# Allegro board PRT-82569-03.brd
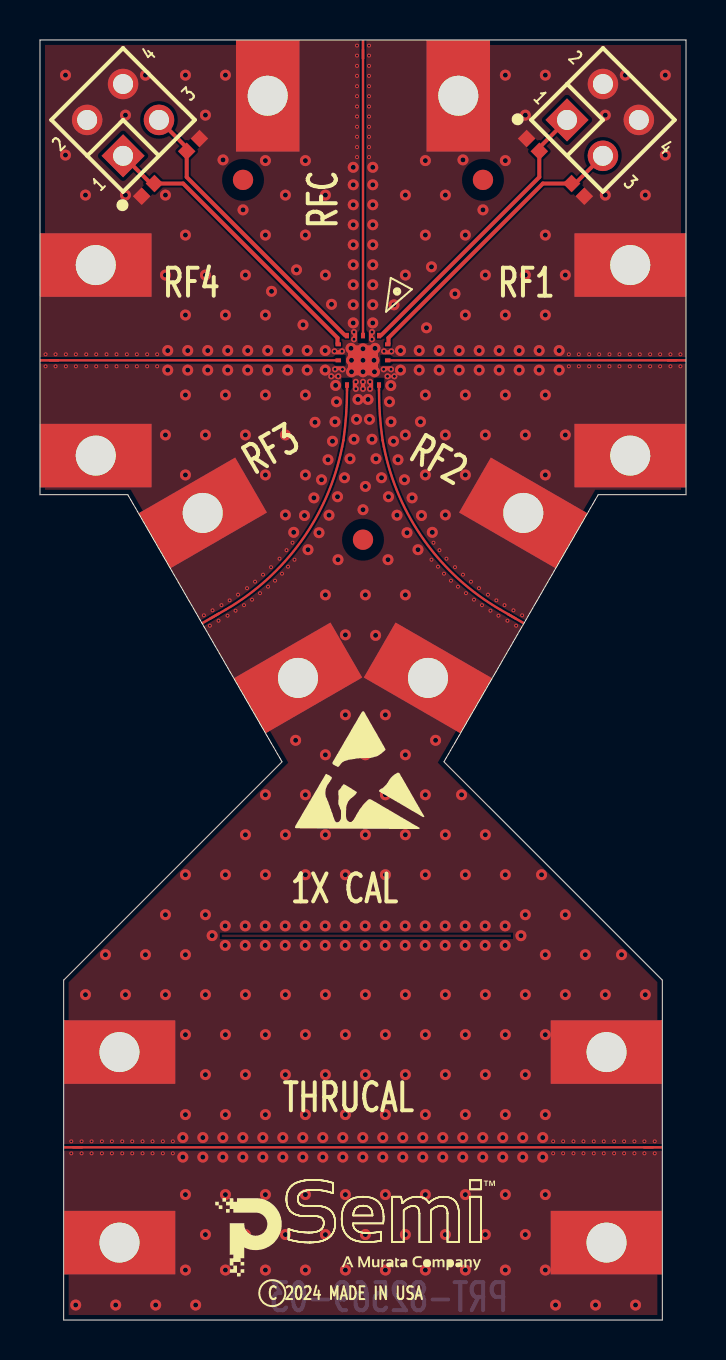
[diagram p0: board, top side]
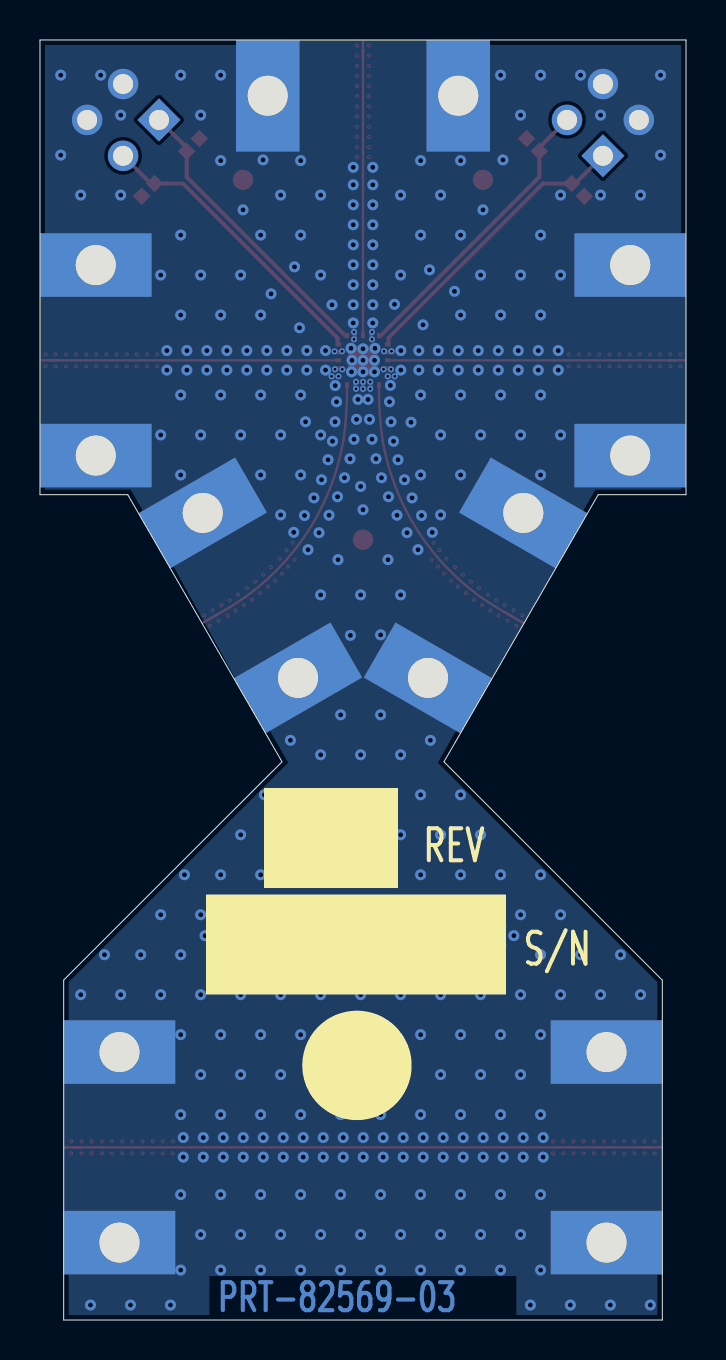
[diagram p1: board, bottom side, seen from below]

Outline 32.31 x 64.03 mm; copper layers: TOP, LAYER_2, LAYER_3, BOTTOM. Coordinates in mm from the lower left corner of the outline.
Outline path: 0,64.03 0,41.29 4.39,41.29 12.11,27.92 1.19,17 1.19,0 31.13,0 31.13,17 20.2,27.92 27.92,41.29 32.31,41.29 32.31,64.03 0,64.03

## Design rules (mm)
constraint set DEFAULT: min track width 0.1

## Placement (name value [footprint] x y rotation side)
C1  -  [CAPC1005X55N]  5.41 56.54 225 top
C2  -  [CAPC1005X55N]  7.66 58.79 45 top
C3  -  [CAPC1005X55N]  24.66 58.79 135 top
C4  -  [CAPC1005X55N]  26.91 56.54 315 top
J1  -  [SOUTHWESTMCW_1092-01A-6]  32.31 48.01 270 top
J3  -  [SOUTHWESTMCW_1092-01A-6]  24.2 34.85 240 top
J4  -  [SOUTHWESTMCW_1092-01A-6]  0 48.01 90 top
J5  -  [SOUTHWESTMCW_1092-01A-6]  8.11 34.85 120 top
J6  -  [SOUTHWESTMCW_1092-01A-6]  16.16 64.03 0 top
J7  -  [SOUTHWESTMCW_1092-01A-6]  1.19 8.64 90 top
J8  -  [SOUTHWESTMCW_1092-01A-6]  31.13 8.64 270 top
NOREF  -  []  -1.59 17.29 0 top
NOREF#2  -  []  0 64.03 0 top
NOREF#3  -  []  -13.93 -48.48 0 top
NOREF#4  -  [unnamed#2]  22.16 57.04 0 top
NOREF#5  -  [unnamed#2]  10.16 57.04 0 top
NOREF#6  -  []  14.47 49.58 0 top
NOREF#7  -  []  -1.21 -32.11 0 top
NOREF#8  -  []  84.01 -62.84 0 top
NOREF#9  -  []  15.98 27.3 359.7 top
NOREF#10  -  [unnamed#2]  16.16 39.04 0 top
NOREF#11  -  []  72.48 60.67 0 top
NOREF#12  -  []  -187.79 90.39 0 top
NOREF#13  -  []  8.76 2.1 0 top
NOREF#14  -  []  1.19 0 0 top
NOREF#15  -  []  31.13 0 90 top
NOREF#16  -  []  1.89 22.9 270 top
NOREF#17  -  []  16.5 12.67 180 bottom
P1  -  [HDR2X2]  4.16 58.24 45 top
P2  -  [HDR2X2]  26.36 60.04 315 top
U1  -  [IC_LGA_3P0X3P0_21P]  16.16 48.01 270 top

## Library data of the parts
C1-C4 = CAP_DNI
J1 J3-J8 = CN_1092-01A-6
P1 P2 = HDR_2X2_M1
U1 = IC_SHAGGY_LGA_21P

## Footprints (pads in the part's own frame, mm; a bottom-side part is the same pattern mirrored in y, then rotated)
CAPC1005X55N
  rect 0.62x0.62 smd: 1(-0.45,0) 2(0.45,0)
HDR2X2
  rect 1.524x1.524 hole 1: 1(0,0)
  round 1.524 hole 1: 2(0,2.54) 3(2.54,0) 4(2.54,2.54)
IC_LGA_3P0X3P0_21P
  rect 0.275x0.2 smd: 1(-1.238,0.8) 2(-1.238,0.4) 3(-1.238,0) 4(-1.238,-0.4) 5(-1.238,-0.8) 11(1.238,-0.8) 12(1.238,-0.4) 13(1.238,0) 14(1.238,0.4) 15(1.238,0.8)
  rect 0.2x0.275 smd: 6(-0.8,-1.238) 7(-0.4,-1.238) 8(0,-1.238) 9(0.4,-1.238) 10(0.8,-1.238) 16(0.8,1.238) 17(0.4,1.238) 18(0,1.238) 19(-0.4,1.238) 20(-0.8,1.238)
  rrect 1.5x1.5 smd: 21(0,0)
SOUTHWESTMCW_1092-01A-6
  rect 0.127x0.953 smd: 1(0,-0.477)
  rect 3.175x5.58 hole 2: 2(-4.765,-2.79) 3(4.765,-2.79)
unnamed#2
  round 1.016 smd: (0,0)

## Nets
GND: C1.2 C2.2 C3.2 C4.2 J1.2 J1.3(GND#3) J3.2 J3.3(GND#3) J4.2 J4.3(GND#3) J5.2 J5.3(GND#3) J6.2 J6.3(GND#3) J7.2 J7.3(GND#3) J8.2 J8.3(GND#3) P1.2 P1.4(PIN4) P2.2 P2.4(PIN4) U1.2 U1.4 U1.7 U1.9 U1.10 U1.12 U1.13 U1.14 U1.16 U1.17 U1.19 U1.21
V1: C3.1 P2.1 U1.1
V2: C4.1 P2.3 U1.20
VDD: C1.1 P1.1 U1.6
VSS: C2.1 P1.3 U1.5(VSS_EXT)
RF1: J1.1 U1.18
RF2: J3.1 U1.15
RF3: J5.1 U1.11
RF4: J4.1 U1.8
RFC: J6.1 U1.3
N5115443: J7.1 J8.1

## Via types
v1: diameter 0.55, hole 0.25, TOP to BOTTOM, 384 vias
v2: diameter 0.2, hole 0.1, TOP to LAYER_2, 164 vias
v3: diameter 0.304, hole 0.152, TOP to BOTTOM, 22 vias

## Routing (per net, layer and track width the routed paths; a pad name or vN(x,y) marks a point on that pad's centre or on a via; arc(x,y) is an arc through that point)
GND: length 4.3
  TOP w0.1: v3(16.16,46.93) U1.13 v3(16.16,46.58) ; v3(15.8,46.93) 15.76,46.89 U1.12 15.76,46.62 v3(15.8,46.58) ; v3(15.13,47.56) 15.08,47.61 U1.9 14.8,47.61 v3(14.76,47.56) ; v3(14.73,48.46) 14.76,48.46 14.81,48.41 U1.7 14.97,48.46 15.1,48.46 v3(15.11,48.46) ; v3(17.73,47.21) U1.16 17.38,47.21 v3(17.38,47.21) ; v3(16.61,49.06) 16.61,49.2 U1.2 16.56,49.37 v3(16.61,49.42) ; v3(16.51,46.58) 16.56,46.63 U1.14 16.51,46.82 v3(16.51,46.93) ; v3(15.71,49.06) 15.71,49.2 U1.4 15.76,49.38 v3(15.71,49.43) ; v3(17.56,47.56) 17.53,47.56 17.48,47.61 U1.17 17.34,47.56 v3(17.19,47.56) ; v3(17.58,48.46) 17.53,48.41 U1.19 17.28,48.41 17.23,48.46 v3(17.21,48.46) ; v3(14.92,47.21) v3(14.57,47.21)
  vias: v1(1.28,62.27) v1(1.28,58.27) v1(1.79,0.75) v1(2.28,56.27) v1(2.28,16.27) v1(3.28,18.27) v1(3.79,0.75) v1(4.28,60.27) v1(4.28,56.27) v1(4.28,16.27) v1(5.28,62.27) v1(5.28,18.27) v1(5.79,0.75) v1(6.28,56.27) v1(6.28,52.27) v1(6.28,44.27) v1(6.28,20.27) v1(6.28,16.27) v1(6.39,48.5) v1(6.39,47.52) v1(7.14,9.13) v1(7.14,8.15) v1(7.28,62.27) v1(7.28,54.27) v1(7.28,50.27) v1(7.28,46.27) v1(7.28,42.27) v1(7.28,22.27) v1(7.28,18.27) v1(7.28,14.27) v1(7.28,10.27) v1(7.28,6.27) v1(7.28,2.5) v1(7.39,48.5) v1(7.39,47.52) v1(7.79,0.75) v1(8.14,9.13) v1(8.14,8.15) v1(8.28,60.27) v1(8.28,52.27) v1(8.28,44.27) v1(8.28,20.27) v1(8.28,16.27) v1(8.28,12.27) v1(8.28,4.27) v1(8.39,48.5) v1(8.39,47.52) v1(8.61,19.23) v1(9.16,58.04) v1(9.14,9.13) v1(9.14,8.15) v1(9.28,62.27) v1(9.28,50.27) v1(9.28,46.27) v1(9.28,22.27) v1(9.26,19.72) v1(9.26,18.74) v1(9.28,14.27) v1(9.28,10.27) v1(9.28,6.27) v1(9.28,2.5) v1(9.39,48.5) v1(9.39,47.52) v1(10.16,55.54) v1(10.14,9.13) v1(10.14,8.15) v1(10.28,52.27) v1(10.28,44.27) v1(10.28,24.27) v1(10.26,19.72) v1(10.26,18.74) v1(10.28,16.27) v1(10.28,12.27) v1(10.28,4.27) v1(10.39,48.5) v1(10.39,47.52) v1(11.14,9.13) v1(11.14,8.15) v1(11.28,58) v1(11.28,54.27) v1(11.28,50.27) v1(11.28,46.27) v1(11.28,42.27) v1(11.28,26.27) v1(11.28,22.27) v1(11.26,19.72) v1(11.26,18.74) v1(11.28,14.27) v1(11.28,10.27) v1(11.28,6.27) v1(11.28,2.5) v1(11.39,48.5) v1(11.39,47.52) v1(11.58,51.46) v1(12.14,9.13) v1(12.14,8.15) v1(12.28,56.27) v1(12.28,44.27) v1(12.28,40.27) v1(12.28,24.27) v1(12.26,19.72) v1(12.26,18.74) v1(12.28,16.27) v1(12.28,12.27) v1(12.28,4.27) v1(12.39,48.5) v1(12.39,47.52) v1(12.69,39.4) v1(12.79,29) v1(12.83,52.54) v1(13.16,49.79) v1(13.14,9.13) v1(13.14,8.15) v1(13.28,58) v1(13.28,54.27) v1(13.28,46.27) v1(13.28,42.27) v1(13.23,40.25) v1(13.28,26.27) v1(13.28,22.27) v1(13.26,19.72) v1(13.26,18.74) v1(13.28,14.27) v1(13.28,10.27) v1(13.28,6.27) v1(13.28,2.5) v1(13.36,48.5) v1(13.36,47.52) v1(13.41,38.54) v1(13.7,41.13) v1(13.76,44.91) v1(13.96,39.39) v1(14.08,42.04) v1(14.14,9.13) v1(14.14,8.15) v1(14.28,56.27) v1(14.28,52.27) v1(14.26,48.5) v1(14.26,47.52) v1(14.28,36.27) v1(14.28,28.27) v1(14.28,24.27) v1(14.26,19.72) v1(14.26,18.74) v1(14.28,16.27) v1(14.28,12.27) v1(14.28,4.27) v1(14.41,43.04) v1(14.46,40.26) v1(14.58,50.81) v1(14.63,43.96) v1(14.79,46.76) v1(14.76,44.94) v1(14.83,45.94) v1(14.88,41.19) v1(14.91,38.04) v1(15.14,9.13) v1(15.14,8.15) v1(15.23,42.14) v1(15.28,34.27) v1(15.28,30.27) v1(15.28,26.27) v1(15.28,22.27) v1(15.26,19.72) v1(15.26,18.74) v1(15.28,14.27) v1(15.28,10.27) v1(15.28,6.27) v1(15.28,2.5) v1(15.51,43.09) v1(15.56,48.61) v1(15.58,48.01) v1(15.58,47.44) v1(15.67,57.66) v1(15.67,56.79) v1(15.67,55.79) v1(15.67,54.79) v1(15.67,53.79) v1(15.67,52.79) v1(15.67,51.79) v1(15.67,50.79) v1(15.67,49.88) v1(15.71,44.06) v1(15.9,46.05) v1(15.83,45.05) v1(16.16,48.59) v1(16.16,48.01) v1(16.16,47.44) v1(16.16,40.54) v1(16.14,9.13) v1(16.14,8.15) v1(16.28,41.7) v1(16.28,36.27) v1(16.28,28.27) v1(16.28,24.27) v1(16.26,19.72) v1(16.26,18.74) v1(16.28,16.27) v1(16.28,12.27) v1(16.28,4.27) v1(16.41,46.05) v1(16.48,45.05) v1(16.64,57.66) v1(16.64,56.79) v1(16.64,55.79) v1(16.64,54.79) v1(16.64,53.79) v1(16.64,52.79) v1(16.64,51.79) v1(16.64,50.79) v1(16.64,49.88) v1(16.61,44.06) v1(16.76,48.61) v1(16.71,48.01) v1(16.73,47.44) v1(16.79,34.25) v1(16.81,43.09) v1(17.08,42.14) v1(17.14,9.13) v1(17.14,8.15) v1(17.27,30.27) v1(17.27,26.27) v1(17.27,22.27) v1(17.26,19.72) v1(17.26,18.74) v1(17.27,14.27) v1(17.27,10.27) v1(17.27,6.27) v1(17.27,2.5) v1(17.41,38.04) v1(17.48,45.94) v1(17.43,41.19) v1(17.55,46.75) v1(17.56,44.94) v1(17.68,43.96) v1(17.71,50.79) v1(17.86,40.26) v1(17.91,43.04) v1(18.03,48.5) v1(18.03,47.52) v1(18.14,9.13) v1(18.14,8.15) v1(18.27,56.27) v1(18.27,52.27) v1(18.27,44.27) v1(18.23,42.04) v1(18.27,36.27) v1(18.27,28.27) v1(18.27,24.27) v1(18.26,19.72) v1(18.26,18.74) v1(18.27,16.27) v1(18.27,12.27) v1(18.27,4.27) v1(18.36,39.39) v1(18.61,41.13) v1(18.97,48.5) v1(18.97,47.52) v1(18.91,38.54) v1(19.03,44.94) v1(19.08,40.25) v1(19.14,9.13) v1(19.14,8.15) v1(19.27,58) v1(19.27,54.27) v1(19.27,46.27) v1(19.27,42.27) v1(19.27,26.27) v1(19.27,22.27) v1(19.26,19.72) v1(19.26,18.74) v1(19.27,14.27) v1(19.27,10.27) v1(19.27,6.27) v1(19.27,2.5) v1(19.33,49.64) v1(19.58,52.69) v1(19.62,39.4) v1(19.79,29) v1(19.97,48.5) v1(19.97,47.52) v1(20.14,9.13) v1(20.14,8.15) v1(20.27,56.27) v1(20.27,44.27) v1(20.27,40.27) v1(20.27,24.27) v1(20.26,19.72) v1(20.26,18.74) v1(20.27,16.27) v1(20.27,12.27) v1(20.27,4.27) v1(20.76,51.34) v1(20.97,48.5) v1(20.97,47.52) v1(21.09,26.27) v1(21.16,58.04) v1(21.14,9.13) v1(21.14,8.15) v1(21.27,54.27) v1(21.27,50.27) v1(21.27,46.27) v1(21.27,42.27) v1(21.27,22.27) v1(21.26,19.72) v1(21.26,18.74) v1(21.27,14.27) v1(21.27,10.27) v1(21.27,6.27) v1(21.27,2.5) v1(21.97,48.5) v1(21.97,47.52) v1(22.16,55.54) v1(22.14,9.13) v1(22.14,8.15) v1(22.27,52.27) v1(22.27,44.27) v1(22.27,24.27) v1(22.26,19.72) v1(22.26,18.74) v1(22.27,16.27) v1(22.27,12.27) v1(22.27,4.27) v1(22.97,48.5) v1(22.97,47.52) v1(23.14,9.13) v1(23.14,8.15) v1(23.27,62.27) v1(23.27,58) v1(23.27,50.27) v1(23.27,46.27) v1(23.27,22.27) v1(23.26,19.72) v1(23.26,18.74) v1(23.27,14.27) v1(23.27,10.27) v1(23.27,6.27) v1(23.27,2.5) v1(23.97,48.5) v1(23.97,47.52) v1(24.06,19.23) v1(24.14,9.13) v1(24.14,8.15) v1(24.27,60.27) v1(24.27,52.27) v1(24.27,44.27) v1(24.27,20.27) v1(24.27,16.27) v1(24.27,12.27) v1(24.27,4.27) v1(24.97,48.5) v1(24.97,47.52) v1(25.09,22.27) v1(25.14,9.13) v1(25.14,8.15) v1(25.27,62.27) v1(25.27,54.27) v1(25.27,50.27) v1(25.27,46.27) v1(25.27,42.27) v1(25.27,18.27) v1(25.27,14.27) v1(25.27,10.27) v1(25.27,6.27) v1(25.27,2.5) v1(25.79,0.75) v1(25.97,48.5) v1(25.97,47.52) v1(26.27,52.27) v1(26.27,44.27) v1(26.27,20.27) v1(26.27,16.27) v1(27.27,18.27) v1(27.79,0.75) v1(28.27,60.27) v1(28.27,56.27) v1(28.27,16.27) v1(29.09,18.27) v1(29.27,62.27) v1(29.79,0.75) v1(30.27,56.27) v1(30.27,16.27) v1(31.27,62.27) v1(31.27,58.27) v2(0.28,48.31) v2(0.28,47.71) v2(0.78,48.31) v2(0.78,47.71) v2(1.3,48.31) v2(1.3,47.71) v2(1.56,8.94) v2(1.56,8.34) v2(1.8,48.31) v2(1.8,47.71) v2(2.08,8.94) v2(2.08,8.34) v2(2.31,48.31) v2(2.31,47.71) v2(2.58,8.94) v2(2.58,8.34) v2(2.81,48.31) v2(2.81,47.71) v2(3.1,8.94) v2(3.1,8.34) v2(3.33,48.31) v2(3.33,47.71) v2(3.6,8.94) v2(3.6,8.34) v2(3.83,48.31) v2(3.83,47.71) v2(4.11,8.94) v2(4.11,8.34) v2(4.34,48.31) v2(4.34,47.71) v2(4.61,8.94) v2(4.61,8.34) v2(4.84,48.31) v2(4.84,47.71) v2(5.13,8.94) v2(5.13,8.34) v2(5.36,48.31) v2(5.36,47.71) v2(5.63,8.94) v2(5.63,8.34) v2(5.86,48.31) v2(5.86,47.71) v2(6.14,8.94) v2(6.14,8.34) v2(6.64,8.94) v2(6.64,8.34) v2(8.2,35.25) v2(8.5,34.73) v2(8.63,35.5) v2(8.93,34.98) v2(9.08,35.76) v2(9.38,35.24) v2(9.49,36) v2(9.78,35.49) v2(9.91,36.29) v2(10.21,35.76) v2(10.36,36.61) v2(10.61,36.04) v2(10.76,36.94) v2(11.01,36.36) v2(11.16,37.29) v2(11.41,36.69) v2(11.56,37.66) v2(11.76,36.99) v2(11.98,38.09) v2(12.11,37.34) v2(12.33,38.51) v2(12.41,37.69) v2(12.63,38.89) v2(12.73,38.04) v2(15.86,63.75) v2(15.86,63.25) v2(15.86,62.74) v2(15.86,62.24) v2(15.86,61.72) v2(15.86,61.22) v2(15.86,60.71) v2(15.86,60.21) v2(15.86,59.69) v2(15.86,59.19) v2(15.86,58.67) v2(15.86,58.17) v2(16.46,63.75) v2(16.46,63.25) v2(16.46,62.74) v2(16.46,62.24) v2(16.46,61.72) v2(16.46,61.22) v2(16.46,60.71) v2(16.46,60.21) v2(16.46,59.69) v2(16.46,59.19) v2(16.46,58.67) v2(16.46,58.17) v2(19.58,38.04) v2(19.68,38.89) v2(19.98,38.51) v2(19.91,37.69) v2(20.21,37.34) v2(20.33,38.09) v2(20.56,36.99) v2(20.76,37.66) v2(20.91,36.69) v2(21.16,37.29) v2(21.31,36.36) v2(21.56,36.94) v2(21.71,36.04) v2(21.96,36.61) v2(22.11,35.76) v2(22.41,36.29) v2(22.53,35.49) v2(22.83,36) v2(22.93,35.24) v2(23.23,35.76) v2(23.38,34.98) v2(23.68,35.5) v2(23.81,34.73) v2(24.11,35.25) v2(25.67,8.94) v2(25.67,8.34) v2(26.17,8.94) v2(26.17,8.34) v2(26.45,48.31) v2(26.45,47.71) v2(26.68,8.94) v2(26.68,8.34) v2(26.95,48.31) v2(26.95,47.71) v2(27.18,8.94) v2(27.18,8.34) v2(27.47,48.31) v2(27.47,47.71) v2(27.7,8.94) v2(27.7,8.34) v2(27.97,48.31) v2(27.97,47.71) v2(28.2,8.94) v2(28.2,8.34) v2(28.48,48.31) v2(28.48,47.71) v2(28.71,8.94) v2(28.71,8.34) v2(28.98,48.31) v2(28.98,47.71) v2(29.21,8.94) v2(29.21,8.34) v2(29.5,48.31) v2(29.5,47.71) v2(29.73,8.94) v2(29.73,8.34) v2(30,48.31) v2(30,47.71) v2(30.23,8.94) v2(30.23,8.34) v2(30.52,48.31) v2(30.52,47.71) v2(30.75,8.94) v2(30.75,8.34) v2(31.02,48.31) v2(31.02,47.71) v2(31.53,48.31) v2(31.53,47.71) v2(32.03,48.31) v2(32.03,47.71)
V1: length 14.7
  TOP w0.121: U1.1 17.04,49.25
  TOP w0.2: P2.1 24.97,58.65 C3.1 24.97,57.18 17.04,49.25
V2: length 14.8
  TOP w0.121: U1.20 17.43,48.85
  TOP w0.2: 17.43,48.85 17.43,49.13 25.15,56.85 C4.1 26.77,56.85 P2.3
VDD: length 14.8
  TOP w0.121: U1.6 14.88,48.85
  TOP w0.2: 14.88,48.85 14.88,49.13 7.16,56.85 C1.1 5.54,56.85 P1.1
VSS: length 14.7
  TOP w0.121: U1.5 15.27,49.25
  TOP w0.2: 15.27,49.25 7.34,57.18 C2.1 7.34,58.65 P1.3
RF1: length 14.4
  TOP w0.121: U1.18 J1.1
RF2: length 14.3
  TOP w0.121: J3.1 23.04,35.53 arc(19.24,38.97) 17.2,43.68 17.13,44.01 arc(17,45.26) 16.96,46.52 U1.15
RF3: length 14.3
  TOP w0.121: U1.11 15.36,46.52 arc(15.31,45.26) 15.18,44.01 15.11,43.68 arc(13.07,38.97) 9.27,35.53 8.96,35.35 J5.1
RF4: length 14.4
  TOP w0.121: J4.1 U1.8
RFC: length 14.3
  TOP w0.121: U1.3 J6.1
N5115443: length 29
  TOP w0.121: J7.1 J8.1

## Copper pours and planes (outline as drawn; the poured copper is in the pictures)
GND on TOP: 32.31,41.66 32.06,41.66 32.06,41.54 27.77,41.54 27.16,40.48 27.38,40.35 21.03,29.35 20.81,29.48 19.89,27.88 30.88,16.9 30.88,14.99 31.13,14.99 31.13,2.29 30.88,2.29 30.88,0.25 1.44,0.25 1.44,2.29 1.19,2.29 1.19,14.99 1.43,14.99 1.43,16.9 12.42,27.88 11.5,29.48 11.28,29.35 4.93,40.35 5.15,40.48 4.54,41.54 0.25,41.54 0.25,41.66 0,41.66 0,54.36 0.25,54.36 0.25,63.79 9.8,63.79 9.8,64.03 22.51,64.03 22.51,63.78 32.06,63.78 32.06,54.36 32.31,54.36
GND on BOTTOM: 32.31,41.65 32.06,41.65 32.06,41.54 27.77,41.54 27.17,40.48 21.03,29.35 20.81,29.48 19.89,27.88 30.88,16.91 30.88,14.99 31.13,14.99 31.13,2.29 30.88,2.29 30.88,0.25 1.44,0.25 1.44,2.29 1.19,2.29 1.19,14.99 1.44,14.99 1.44,16.9 12.42,27.88 11.5,29.48 11.28,29.35 4.93,40.35 5.15,40.48 4.54,41.54 0.26,41.54 0.25,41.66 0,41.66 0,54.36 0.25,54.36 0.25,63.78 9.8,63.78 9.8,64.03 22.51,64.03 22.51,63.78 32.06,63.78 32.06,54.36 32.31,54.36
GND on LAYER_2: 32.31,41.66 32.06,41.66 32.06,41.54 27.77,41.54 27.16,40.48 27.38,40.35 21.03,29.35 20.81,29.48 19.89,27.88 30.88,16.91 30.88,14.99 31.13,14.99 31.13,2.29 30.88,2.29 30.88,0.25 1.44,0.25 1.44,2.29 1.19,2.29 1.19,14.99 1.43,14.99 1.43,16.9 12.42,27.88 11.5,29.48 11.28,29.35 4.93,40.35 5.15,40.48 4.54,41.54 0.25,41.54 0.25,41.66 0,41.66 0,54.36 0.25,54.36 0.25,63.79 9.8,63.79 9.8,64.03 22.51,64.03 22.51,63.78 32.06,63.78 32.06,54.36 32.31,54.36
GND on LAYER_3: 32.06,41.54 27.77,41.54 27.17,40.48 27.38,40.35 21.03,29.35 20.81,29.48 19.89,27.88 30.88,16.9 30.88,14.99 31.13,14.99 31.13,2.29 30.88,2.29 30.88,0.25 1.44,0.25 1.44,2.29 1.19,2.29 1.19,14.99 1.44,14.99 1.44,16.9 12.42,27.88 11.5,29.48 11.28,29.35 4.93,40.35 5.15,40.48 4.54,41.54 0.25,41.54 0.25,41.66 0,41.66 0,54.36 0.25,54.36 0.25,63.78 9.8,63.78 9.8,64.03 22.51,64.03 22.51,63.78 32.06,63.78 32.06,54.36 32.31,54.36 32.31,41.65 32.06,41.65
RFETCHSHAPENET on TOP: 9.09,19.16 9.09,19.28 23.56,19.28 23.56,19.16

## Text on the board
BOTTOM: LAYER 4 (SECONDARY SIDE) | L4 | PRT-82569-03
Board Geometry/Soldermask Bottom: SOLDER MASK (SECONDARY SIDE) | BM
Ref Des/Silkscreen Bottom: SILKSCREEN (SECONDARY SIDE) | BS
Board Geometry/Outline: BOARD OUTLINE (TOP VIEW) | BD
TOP: LAYER 1 (PRIMARY SIDE) | L1
Board Geometry/Soldermask Top: SOLDER MASK (PRIMARY SIDE) | TM
Ref Des/Silkscreen Top: SILKSCREEN (PRIMARY SIDE) | TS | RF4 | THRUCAL | 1X CAL | RF1 | RF3 | RFC | RF2
LAYER_2: LAYER 2 (GND PLANE) | L2
LAYER_3: LAYER 3 (GND PLANE) | L3
BODY_CENTER: SOLDER PASTE (SECONDARY SIDE) | BP
PASTEMASK_TOP: SOLDER PASTE (PRIMARY SIDE) | TP
User.16: SOLDER PASTE PARTICAL SIZE" <40 MICROMETERS | SOLDER PASTE TYPE: SAC405 (SAC305 IS ACCEPTABLE) | SOLDER PASTE FLUX" NO-CLEAN FLUX | SOLDER PASTE STENCIL TYPE:LASER CUT | SOLDER PASTE STENCIL THICKNESS: < 3.6 MILS | 12. | 13. | 14. | 15. | 16.
User.17: TO PSEMI A MURATA COMPANY. THE INFORMATION IN
User.18: NOTES: UNLESS OTHERWISE SPECIFIED, ALL DIMENSIONS ARE IN METRIC | TRACE WIDTH/SPACE/VIA: | TRACE WIDTHS/SPACING TO BE WITHIN | MINIMUM TRACE WIDTH: | MINIMUM AIR GAP: | MINIMUM VIA PAD DIAMETER: | MATERIAL: | NUMBER OF ELECTRICAL LAYERS IS | MATERIALS AND OVERALL THICKNESS SEE STACKUP DETAIL. | LOAD BOARD AND PREPREG PER IPC-4101.  COPPER FOIL PER IPC-MF-150. | MATERIAL'S GLASS TRANSITION TEMPERATURE (Tg) SHALL BE A MINIMUM OF | 170  CENTIGRADE. | MATERIAL MUST MEET UL796 WITH A FLAMMABILITY RATING OF 94V-0 | VENDOR UL LOGO AND DATE CODE TO BE SCREENED ON THE BOTTOM SIDE. IF NO BOTTOM | SILKSCREEN PROVIDED VENDOR MAY ADD BOTTOM SILKSCREEN. | TOLERANCES: | 6A. LAYER TO LAYER REGISTRATION WITHIN .076mm. | 6B. ALL HOLES TO BE LOCATED WITHIN .076mm OF ORIGINAL CAD DATA. | 6C. ALL HOLES SURROUNDED BY COPPER SHALL HAVE A MINIMUM ANNULAR RING OF .076mm. | 6D. ALL PLATED THROUGH HOLES TO HAVE A MINIMUM .025mm OF PLATING. | 6E. HOLE DIMENSIONS AND TOLERANCES APPLY AFTER PLATING, SEE DRILL HOLE CHART. | 6F. WARP AND TWIST NOT TO EXCEED .254 MM/MM. | EXPOSED COPPER ALONG BOARD EDGE IS ACCEPTABLE, POST PANEL ROUTING PROCESS. | INTERPRET DIMENSIONS AND TOLERANCES PER ANSI Y14.5M. | GERBER FILES CONTAIN BOARD OUTLINE FOR ALIGNMENT PURPOSES, | REMOVE PRIOR TO FABRICATION. | FABRICATE PCB PER IPC-6012, LATEST REVISION, TYPE 3, CLASS 2. | THE DETAILED NOTES AND INSTRUCTIONS ON THIS DRAWING SUPERCEDE IPC REQUIREMENTS. | BARE BOARD ACCEPTANCE PER IPC-A-600, LATEST REVISION. | PLATING OPTIONS: USE 7A | 7A. IAg - IMMERSION SILVER 6-20 MICROINCHES MINIMUM PER IPC-4553. | 7B. SELECTIVE HARD GOLD FINISH IN THE DUT AND POGOPAD AREA(S), CLASS 1 50-100 MICROINCHES | 7C. HASL (HOT AIR SOLDER LEVEL) SMT PADS MUST BE FLAT TO A MAX OF .076mm (.003") ABOVE | APPLY LPI (LIQUID PROTO-IMAGEABLE) SOLDERMASK OVER BARE COPPER (SMOBC) PER IPC-SM-840 | CLASS "T" TO BOTH SIDES OF PCB. SOLDERMASK COLOR TO BE: GREEN | GERBER FILES REFLECT A ZERO OVERSIZE. VENDOR MAY OVERSIZE AS NEEDED, MAX THICKNESS | .020mm. IT IS NOT ACCEPTABLE FOR SOLDERMASK WEBBING TO DISAPPEAR BETWEEN FINE PITCH BALL PADS. | APPLY SILKSCREEN LEGEND USING WHITE NON-CONDUCTIVE EPOXY INK. TRIM SILKSCREEN FROM ALL | EXPOSED COPPER. | VENDOR TO REMOVE NON-FUNCTIONAL PADS FROM INTERNAL LAYERS. | VENDOR MAY ONLY ADD THIEVING OUTSIDE THE BOARD OUTLINE TO COMPENSATE FOR LOW COPPER DENSITY. | REMOVE ALL BURRS AND BREAK SHARP EDGES, INSIDE CORNER MAXIMUM RADIUS 0.381mm. | BARE BOARD ELECTRICAL TEST IS REQUIRED. USE THE SUPPLIED IPC-D-356 NETLIST "PRT-82569-01.IPC". | MATRIX DRAWING: USE 14A | 14A. NO MATRIX DRAWING IS REQUIRED. BOARDS TO BE DELIVERED FULLY ROUTED. | 14B. MATRIX DRAWING PROVIDED, SEE FABRICATION DRAWING SHEET 2 OF 2. | 14C. VENDOR TO GENERATE MATRIX DRAWING. VENDOR GENERATED MATRIX DRAWINGS REQUIRE APPROVAL | PLANARITY:  USE 15A,15B. | 15A. VARIATION OF BUMP PADS IN THE Z AXIS TO BE <=5um. | 15B. ALL VIAS TO BE NON-CONDUCTIVE EPOXY FILLED AND COPPER OVERPLATED AFTER PLATING AND BEFORE FINAL | 15C. ALL OTHER VIAS ARE TO BE PLUGGED AND FILLED WITH SOLDERMASK MATERIAL. | CONTROLLED IMPEDANCE REQUIREMENTS: | VENDOR MAY MODIFY DIELECTRIC THICKNESS BY 25% WITHOUT WRITTEN CONSENT. ANY MODIFICATION | GREATER THAN 25% REQUIRES WRITTEN CONSENT FROM PSEMI. | 16A. NO CONTROLLED IMPEDANCE MEASUREMENTS REQUIRED. | 16B. VENDOR TO PROVIDE TEST COUPON AND IMPEDANCE REPORT. | SHORTS DESIGNED IN BOARD: | NET XXXXXXXXXXXX. | NET XXXXXX TO GND, LAYER 4 | IPC-2221 TEST COUPONS A & B REQUIRED. TEST COUPONS SHALL BE IDENTIFIED AND TRACEABLE TO THE LOT. | TEST COUPONS, DATA, CROSSECTIONS VERIFYING WIDTH AND CERTIFICATES OF CONFORMANCE | SHALL ACCOMPANY ALL SHIPMENTS. MATERIAL VERIFICATION SHALL ALSO BE SENT IN WRITING. | SHIPMENTS WITHOUT THESE CERTIFICATIONS WILL NOT BE ACCEPTED. | DEVIATIONS BY FABRICATION FACILITY TO BE REPORTED TO PSEMI. | 0.10 - 0.20 uM OVER ELECTROLESS PALLADIUM OVER 3-6 uM OF PALLADIUM PER IPC-4552. | MICROINCHES THICK (KNOOP HARDNESS 130-200) OVER NICKEL PLATE IN ACCORDANCE WITH | IPC-A-600, LATEST REVISION, SECTION 4.0, CLASS 3 (200-600 MICROINCHES THICK). | FABRICATE IN ACCORDANCE WITH IPC-6018, START WITH 1/4oz. COPPER | SURFACE. HASL FINISH TO BE USED ON TEST OR PROTOTYPE BOARDS ONLY. THIS FINISH DOES | NOT COMPLY WITH RoHS DIRECTIVES. | 0.1270mm TRACES ON LAYER 1 ARE 50 OHMS, TRANSMISSION LINES_X_+/-5%. | .XXmm (.XXX") TRACES ON LAYER Y ARE 50 OHMS, MICROSTRIP, +/- 10%. | .XXmm (.XXX") TRACES ON LAYER Y ARE 100 OHMS, DIFFERENTIAL, +/- 10%. | BY PSEMI. PANELIZED BOARDS TO HAVE SAME ORIENTATION AND SHALL BE | ROUTED AND RETAINED WITH BREAK AWAY TABS. SEE DETAIL B. SUPPORT RAIL WIDTH TO BE | 6.35mm - 12.7mm WITH 1.52mm FIDUCIALS AND 3.175mm | TOOLING HOLES IN 3 CORNERS, PANELIZED SOLDERPASTE GERBER TO BE SUBMITTED TO | PSEMI. | SURFACE FINISH. NON-CONDUCTIVE EPOXY (SAN_EI 900 OR EQUIVALENT) IS RECOMMENDED. | EPOXY SHALL NOT PROTRUDE FROM HOLES. THIS APPLIES TO ALL VIAS THAT ARE EXPOSED ON | BOTH SIDES. A SMOOTH COPLANAR FINISH IS REQUIRED WHEN EXPOSED BY SOLDERMASK. | OUTER LAYERS= | INNER LAYERS= | SIDES. | 0.20mm | 0.1016 | NA | 4 | 0.127mm | 20% OF GERBER DATA. | USE 16A | 10%. | BOTH | NO | 4. | 5. | 6. | 7. | 8. | 9. | 10. | 11. | 12. | 13. | 14. | 15. | 16. | 17. | 18. | 1. | 2. | 3. | 19.
User.19: TOLERANCES UNLESS OTHERWISE NOTED | DIMENSIONS IN mm/[Inches] | X.X | X.XX | X.XXX | X.XXXX | ANGLES | = +/- .2.5/[.1] | = +/- .25/[.01] | = +/- .127/[.005] | = +/- .0127/[.0005] | = +/- 1/2 DEG | THIS DOCUMENT CONTAINS INFORMATION PROPRIETARY TO | PSEMI. THE INFORMATION IN THIS DOCUMENT IS NOT TO | BE USED OR DUPLICATED IN ANY MANNER WITHOUT THE | PRIOR APPROVAL OF PSEMI. | MATERIAL | FINISH | DO NOT SCALE DRAWING | CONTRACT NO. | DRAWN | CHECKED | ISSUED | REVISIED BY | ZONE | APPROVALS | REV | DATE | COMPANY | TITLE | SIZE | SCALE: | RoHS COMPLIANCE | RELEASE DATE | REVISIONS | DWG NO. | 9380 Carroll Park Drive | San Diego, CA, 92121 | (858)731-9400 Phone | (858)731-9499 Fax | SHEET: | SH | OF | 03/25/2024 | 10/17/2022 | (Make like PRT-80002-01) | M. MOREY | R.ALIDIO | 01 | ---- | mm/dd/yy | 1 | 2 | NONE | PCB, | PE42546/PE42548 EVB (LGA) | B | PRT-82569 | 03 | D | C | A | 4 | 3
User.20: TOLERANCES UNLESS OTHERWISE NOTED | DIMENSIONS IN mm/[Inches] | X.X | X.XX | X.XXX | X.XXXX | ANGLES | = +/- .2.5/[.1] | = +/- .25/[.01] | = +/- .127/[.005] | = +/- .0127/[.0005] | = +/- 1/2 DEG | OF | THIS DOCUMENT CONTAINS INFORMATION PROPRIETARY TO | PSEMI. THE INFORMATION IN THIS DOCUMENT IS NOT TO | BE USED OR DUPLICATED IN ANY MANNER WITHOUT THE | PRIOR APPROVAL OF PSEMI. | MATERIAL | FINISH | DO NOT SCALE DRAWING | CONTRACT NO. | DRAWN | CHECKED | ISSUED | REVISIED BY | ZONE | APPROVALS | REV | DATE | COMPANY | TITLE | SIZE | SCALE: | RoHS COMPLIANCE | RELEASE DATE | REVISIONS | DWG NO. | 9380 Carroll Park Drive | San Diego, CA, 92121 | (858)731-9400 Phone | (858)731-9499 Fax | SHEET: | SH | 03/25/2024 | 10/23/2022 | M. MOREY | R.ALIDIO | 01 | ---- | mm/dd/yy | 1 | NONE | PCA, | PE42546 Shaggy LGA EVK Board | B | PRT-82568 | 03 | D | C | A | 4 | 3 | ASSEMBLY PRIMARY SIDE | 2
User.21: THIS DOCUMENT CONTAINS INFORMATION PROPRIETARY TO | PSEMI. THE INFORMATION IN THIS DOCUMENT IS NOT TO | BE USED OR DUPLICATED IN ANY MANNER WITHOUT THE | PRIOR APPROVAL OF PSEMI. | REV | OF | SH | SHEET: | DWG NO. | RoHS COMPLIANCE | RELEASE DATE | SIZE | SCALE: | 2 | NONE | 01 | PRT-77450 | PRT-80002 | B | D | C | A | 1 | 3 | 4
User.22: THIS DOCUMENT CONTAINS INFORMATION PROPRIETARY TO | PSEMI. THE INFORMATION IN THIS DOCUMENT IS NOT TO | BE USED OR DUPLICATED IN ANY MANNER WITHOUT THE | PRIOR APPROVAL OF PSEMI. | SIZE | SCALE: | RoHS COMPLIANCE | RELEASE DATE | DWG NO. | SHEET: | SH | OF | REV | 2 | NONE | B | PRT-80002 | 01 | D | C | A | 4 | 3 | 1
User.37: FIG | FINISHED SIZE | 0.1524 | 0.25 | 1.0 | 2.0 | ALL UNITS ARE IN MILLIMETERS | TOLERANCE | +0.0/-0.1524 | +0.075/-0.075 | PLATED | QTY | 22 | 384 | 8 | 14 | 428 | TOTAL HOLES: | TOP to BOTTOM
User.39: FIG | FINISHED SIZE | 0.1 | ALL UNITS ARE IN MILLIMETERS | TOLERANCE | +0.027/-0.1 | PLATED | QTY | 164 | TOTAL HOLES: | TOP to LAYER_2
User.40: C 2022 MADE IN USA | 2 | 1 | 4 | C1 | 3 | C2 | C3 | C4 | J7 | RF4 | RF1 | J1 | J8 | J5 | RF3 | P1 | J6 | RFC | P2 | RF2 | J3 | U1
